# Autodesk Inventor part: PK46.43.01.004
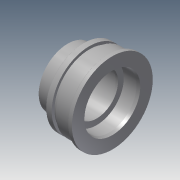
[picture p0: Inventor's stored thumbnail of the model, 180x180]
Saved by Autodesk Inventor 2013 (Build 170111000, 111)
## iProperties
Shininess: 64.0
Length Units: 11269
Angle Units: 11279
Time Units: 11290
Mass Units: 11283
Length Display Precision: 3
Angle Display Precision: 2
Compacted: True
Part Number: PK46.43.01.004
Document SubType Name: Modeling
Created: 2004-11
Material: Steel, Mild
Designer: ELarisa
Manufacturer: Standard
Standards Organization: Custom
Density: 7.86 g/cm^3
Density: 0.0
Volumn: 0.0
Area: 0.0
PropertySet Name: Model Information
Control State: 0
Master: False
Checked Out: False
Checked Out Date: 2008-10-09
Last Check In Date: 2008-10-09
Author: ELarisa
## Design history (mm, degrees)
revolve "Вращение1" stored, may be unused: angle "d17" = 90 deg
chamfer "Фаска1" distance "d18" = 1; stored, may be unused: second distance "d19" = 2, angle "d20" = 45 deg
body "Solid1"
sketch "Эскиз1"
  geometry: L1 (0, 0)-(0, 48); L2 (0, 48)-(26, 48); L3 (26, 48)-(26, 62.5); L4 (67, 62.5)-(67, 67); L5 (67, 67)-(74, 67); L6 (74, 67)-(74, 0); L7 (74, 0)-(0, 0); L8 (4, 35.5)-(4, 37.5); L9 (4, 37.5)-(44, 37.5); L10 (44, 37.5)-(44, 35.5); L11 (44, 35.5)-(48, 35.5); L12 (48, 35.5)-(48, 45); L13 (48, 45)-(69, 45); L14 (69, 45)-(74, 46.34); L15 (36, 62.5)-(36, 57.9); L16 (36, 57.9)-(43, 57.9); L17 (43, 57.9)-(43, 62.5); L18 (26, 62.5)-(36, 62.5); L19 (43, 62.5)-(67, 62.5); L20 (4, 35.5)-(0, 35.5)
  constraints: 40 end point, 9 parallel, 6 perpendicular, 2 collinear, 2 point on line, 1 vertical, 1 other
  dimensions: "d0" = 74 distance of L6.end L1.start; "d1" = 7 distance of L4.end L5.end; "d2" = 43 distance between parallel lines of L1 L17; "d3" = 7 distance of L15.end L16.end; "d4" = 26 distance of L1.end L2.end; "d5" = 5 horizontal distance of L13.end L14.end; "d6" = 26 distance between parallel lines of L6 L12; "d8" = 40 distance of L8.end L9.end; "d9" = 67 distance between parallel lines of L5 L7; "d10" = 62.5 distance between parallel lines of L19 L7; "d11" = 57.9 distance between parallel lines of L7 L16; "d12" = 48 distance between parallel lines of L7 L2; "d13" = 45 distance between parallel lines of L7 L13; "d14" = 35.5 distance between parallel lines of L7 L11; "d15" = 37.5 distance between parallel lines of L7 L9; "d16" = 4 distance of L8.start L20.end; "d21" = 15 deg angle of L13 L14
